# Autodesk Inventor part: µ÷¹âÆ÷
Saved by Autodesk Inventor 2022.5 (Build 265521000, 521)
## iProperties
Created: 2024-07
Part Number: µ÷¹âÆ÷
Material: Generic
Document SubType Name: Modeling
Designer: AdminForWorker
Density: 1 g/cm^3
Appearance: Default
Title: µ÷¹âÆ÷
Author: AdminForWorker
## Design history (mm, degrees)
feature "Body1"
body "Solid1"
